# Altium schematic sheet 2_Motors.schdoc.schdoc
size 309 x 223 mm; Symbol: Sheet-Symbol_A4; Device: Sheet-Symbol_A4; @Project Name: AstrOnStep; @Page Count: 2; @Update Date: 2024-04-19; @Create Date: 2024-04-17; @Schematic Name: AstrOnStep SCH; @Page No: 2; @Page Name: Motors.AstrOnStep SCH; Company: EasyEDA.com; Reviewed: EasyEDA; Version: V0.1; Page Size: A4; Part Number: JLCPCB-002; Drawn: EasyEDA
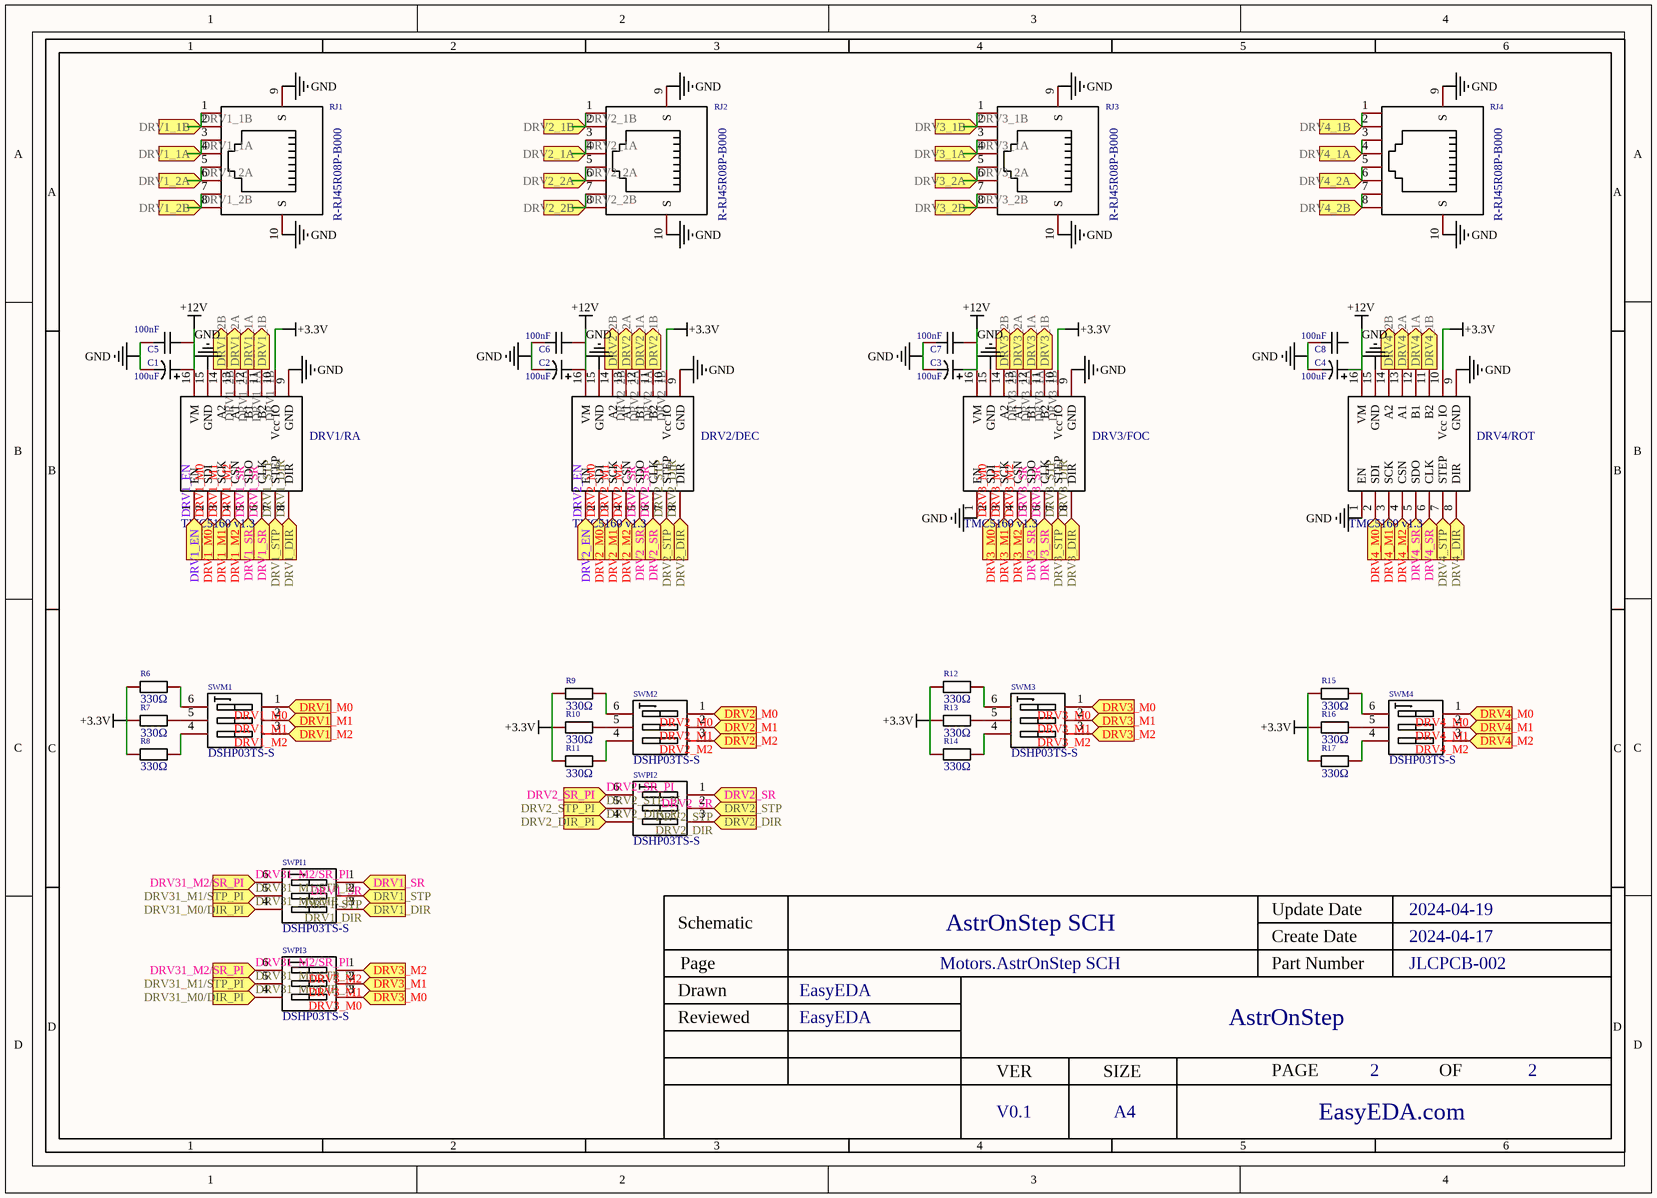
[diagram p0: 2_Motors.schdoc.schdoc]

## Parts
C1  100uF  [CAP-SMD_BD6.3-L6.6-W6.6-LS7.3-FD]
C2  100uF  [CAP-SMD_BD6.3-L6.6-W6.6-LS7.3-FD]
C3  100uF  [CAP-SMD_BD6.3-L6.6-W6.6-LS7.3-FD]
C4  100uF  [CAP-SMD_BD6.3-L6.6-W6.6-LS7.3-FD]
C5  100nF  [C0603]
C6  100nF  [C0603]
C7  100nF  [C0603]
C8  100nF  [C0603]
DRV1/RA  TMC5160 v1.3  [TMC5160]
DRV2/DEC  TMC5160 v1.3  [TMC5160]
DRV3/FOC  TMC5160 v1.3  [TMC5160]
DRV4/ROT  TMC5160 v1.3  [TMC5160]
R6  330Ω  [R0402]
R7  330Ω  [R0402]
R8  330Ω  [R0402]
R9  330Ω  [R0402]
R10  330Ω  [R0402]
R11  330Ω  [R0402]
R12  330Ω  [R0402]
R13  330Ω  [R0402]
R14  330Ω  [R0402]
R15  330Ω  [R0402]
R16  330Ω  [R0402]
R17  330Ω  [R0402]
RJ1  R-RJ45R08P-B000  [RJ45-TH_R-RJ45R08P-B000]
RJ2  R-RJ45R08P-B000  [RJ45-TH_R-RJ45R08P-B000]
RJ3  R-RJ45R08P-B000  [RJ45-TH_R-RJ45R08P-B000]
RJ4  R-RJ45R08P-B000  [RJ45-TH_R-RJ45R08P-B000]
SWM1  DSHP03TS-S  [SW-SMD_DSHP03TS-S]
SWM2  DSHP03TS-S  [SW-SMD_DSHP03TS-S]
SWM3  DSHP03TS-S  [SW-SMD_DSHP03TS-S]
SWM4  DSHP03TS-S  [SW-SMD_DSHP03TS-S]
SWPI1  DSHP03TS-S  [SW-SMD_DSHP03TS-S]
SWPI2  DSHP03TS-S  [SW-SMD_DSHP03TS-S]
SWPI3  DSHP03TS-S  [SW-SMD_DSHP03TS-S]

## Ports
DRV1_1A (in), DRV1_1A (out), DRV1_1B (in), DRV1_1B (out), DRV1_2A (in), DRV1_2A (out), DRV1_2B (in), DRV1_2B (out), DRV1_DIR (in), DRV1_EN (in), DRV1_M0 (in), DRV1_M1 (in), DRV1_M2 (in), DRV1_SR (in), DRV1_STP (in), DRV2_1A (in), DRV2_1A (out), DRV2_1B (in), DRV2_1B (out), DRV2_2A (in), DRV2_2A (out), DRV2_2B (in), DRV2_2B (out), DRV2_DIR (in), DRV2_DIR_PI (in), DRV2_EN (in), DRV2_M0 (in), DRV2_M1 (in), DRV2_M2 (in), DRV2_SR (in), DRV2_SR_PI (in), DRV2_STP (in), DRV2_STP_PI (in), DRV3_1A (in), DRV3_1A (out), DRV3_1B (in), DRV3_1B (out), DRV3_2A (in), DRV3_2A (out), DRV3_2B (in), DRV3_2B (out), DRV3_DIR (in), DRV3_M0 (in), DRV3_M1 (in), DRV3_M2 (in), DRV3_SR (in), DRV3_STP (in), DRV4_1A (in), DRV4_1A (out), DRV4_1B (in), DRV4_1B (out), DRV4_2A (in), DRV4_2A (out), DRV4_2B (in), DRV4_2B (out), DRV4_DIR (in), DRV4_M0 (in), DRV4_M1 (in), DRV4_M2 (in), DRV4_SR (in), DRV4_STP (in), DRV31_M0/DIR_PI (in), DRV31_M1/STP_PI (in), DRV31_M2/SR_PI (in)

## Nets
+3.3V: DRV1/RA.10(Vcc_IO) DRV2/DEC.10(Vcc_IO) DRV3/FOC.10(Vcc_IO) DRV4/ROT.10(Vcc_IO) R6.2 R7.2 R8.2 R9.2 R10.2 R11.2 R12.2 R13.2 R14.2 R15.2 R16.2 R17.2
+12V: C1.1 C2.1 C3.1 C4.1 C5.1 C6.1 C7.1 DRV1/RA.16(VM) DRV2/DEC.16(VM) DRV3/FOC.16(VM) DRV4/ROT.16(VM)
GND: C1.2 C2.2 C3.2 C4.2 C5.2 C6.2 C7.2 C8.2 DRV1/RA.9(GND) DRV1/RA.15(GND) DRV2/DEC.9(GND) DRV2/DEC.15(GND) DRV3/FOC.1(EN) DRV3/FOC.9(GND) DRV3/FOC.15(GND) DRV4/ROT.1(EN) DRV4/ROT.9(GND) DRV4/ROT.15(GND) RJ1.9(S) RJ1.10(S) RJ2.9(S) RJ2.10(S) RJ3.9(S) RJ3.10(S) RJ4.9(S) RJ4.10(S)
DRV1_1A: DRV1/RA.12(B1) RJ1.3 RJ1.4 ; port DRV1_1A
DRV1_1B: DRV1/RA.11(B2) RJ1.1 RJ1.2 ; port DRV1_1B
DRV1_2A: DRV1/RA.13(A1) RJ1.5 RJ1.6 ; port DRV1_2A
DRV1_2B: DRV1/RA.14(A2) RJ1.7 RJ1.8 ; port DRV1_2B
DRV1_DIR: DRV1/RA.8(DIR) SWPI1.3 ; port DRV1_DIR
DRV1_EN: DRV1/RA.1(EN) ; port DRV1_EN
DRV1_M0: DRV1/RA.2(SDI) SWM1.1 ; port DRV1_M0
DRV1_M1: DRV1/RA.3(SCK) SWM1.2 ; port DRV1_M1
DRV1_M2: DRV1/RA.4(CSN) SWM1.3 ; port DRV1_M2
DRV1_SR: DRV1/RA.5(SDO) DRV1/RA.6(CLK) SWPI1.1 ; port DRV1_SR
DRV1_STP: DRV1/RA.7(STEP) SWPI1.2 ; port DRV1_STP
DRV2_1A: DRV2/DEC.12(B1) RJ2.3 RJ2.4 ; port DRV2_1A
DRV2_1B: DRV2/DEC.11(B2) RJ2.1 RJ2.2 ; port DRV2_1B
DRV2_2A: DRV2/DEC.13(A1) RJ2.5 RJ2.6 ; port DRV2_2A
DRV2_2B: DRV2/DEC.14(A2) RJ2.7 RJ2.8 ; port DRV2_2B
DRV2_DIR: DRV2/DEC.8(DIR) SWPI2.3 ; port DRV2_DIR
DRV2_DIR_PI: SWPI2.4 ; port DRV2_DIR_PI
DRV2_EN: DRV2/DEC.1(EN) ; port DRV2_EN
DRV2_M0: DRV2/DEC.2(SDI) SWM2.1 ; port DRV2_M0
DRV2_M1: DRV2/DEC.3(SCK) SWM2.2 ; port DRV2_M1
DRV2_M2: DRV2/DEC.4(CSN) SWM2.3 ; port DRV2_M2
DRV2_SR: DRV2/DEC.5(SDO) DRV2/DEC.6(CLK) SWPI2.1 ; port DRV2_SR
DRV2_SR_PI: SWPI2.6 ; port DRV2_SR_PI
DRV2_STP: DRV2/DEC.7(STEP) SWPI2.2 ; port DRV2_STP
DRV2_STP_PI: SWPI2.5 ; port DRV2_STP_PI
DRV3_1A: DRV3/FOC.12(B1) RJ3.3 RJ3.4 ; port DRV3_1A
DRV3_1B: DRV3/FOC.11(B2) RJ3.1 RJ3.2 ; port DRV3_1B
DRV3_2A: DRV3/FOC.13(A1) RJ3.5 RJ3.6 ; port DRV3_2A
DRV3_2B: DRV3/FOC.14(A2) RJ3.7 RJ3.8 ; port DRV3_2B
DRV3_DIR: DRV3/FOC.8(DIR) ; port DRV3_DIR
DRV3_M0: DRV3/FOC.2(SDI) SWM3.1 SWPI3.3 ; port DRV3_M0
DRV3_M1: DRV3/FOC.3(SCK) SWM3.2 SWPI3.2 ; port DRV3_M1
DRV3_M2: DRV3/FOC.4(CSN) SWM3.3 SWPI3.1 ; port DRV3_M2
DRV3_SR: DRV3/FOC.5(SDO) DRV3/FOC.6(CLK) ; port DRV3_SR
DRV3_STP: DRV3/FOC.7(STEP) ; port DRV3_STP
DRV4_1A: DRV4/ROT.12(B1) RJ4.3 RJ4.4 ; port DRV4_1A
DRV4_1B: DRV4/ROT.11(B2) RJ4.1 RJ4.2 ; port DRV4_1B
DRV4_2A: DRV4/ROT.13(A1) RJ4.5 RJ4.6 ; port DRV4_2A
DRV4_2B: DRV4/ROT.14(A2) RJ4.7 RJ4.8 ; port DRV4_2B
DRV4_DIR: DRV4/ROT.8(DIR) ; port DRV4_DIR
DRV4_M0: DRV4/ROT.2(SDI) SWM4.1 ; port DRV4_M0
DRV4_M1: DRV4/ROT.3(SCK) SWM4.2 ; port DRV4_M1
DRV4_M2: DRV4/ROT.4(CSN) SWM4.3 ; port DRV4_M2
DRV4_SR: DRV4/ROT.5(SDO) DRV4/ROT.6(CLK) ; port DRV4_SR
DRV4_STP: DRV4/ROT.7(STEP) ; port DRV4_STP
DRV31_M0/DIR_PI: SWPI1.4 SWPI3.4 ; port DRV31_M0/DIR_PI
DRV31_M1/STP_PI: SWPI1.5 SWPI3.5 ; port DRV31_M1/STP_PI
DRV31_M2/SR_PI: SWPI1.6 SWPI3.6 ; port DRV31_M2/SR_PI
NetR6_1: R6.1 SWM1.6
NetR7_1: R7.1 SWM1.5
NetR8_1: R8.1 SWM1.4
NetR9_1: R9.1 SWM2.6
NetR10_1: R10.1 SWM2.5
NetR11_1: R11.1 SWM2.4
NetR12_1: R12.1 SWM3.6
NetR13_1: R13.1 SWM3.5
NetR14_1: R14.1 SWM3.4
NetR15_1: R15.1 SWM4.6
NetR16_1: R16.1 SWM4.5
NetR17_1: R17.1 SWM4.4

Not connected (* = marked no-connect by the designer): C8 1

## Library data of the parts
C1-C4 = RST100UF25V004: Manufacturer: KNSCHA(科尼盛); Add into BOM: yes; Tolerance: ±20%; Ripple Current: 88mA@120Hz; Lifetime @ Temp: 2000hrs@105℃; Description: Capacitance: Tolerance:±20% Tolerance:±20% Rated Voltage: Ripple Current:88mA@120Hz Equivalent Series Resistance(ESR):- φD: L: Lifetime @ Temp:2000hrs@105℃ Operating Temperature:-40℃~+105℃ Operating Temperature:-40℃~+105℃
C5-C8 = CC0603KRX7R9BB104: Manufacturer: YAGEO(国巨); Add into BOM: yes; Tolerance: ±10%; Description: Capacitance:Tolerance:±10%Tolerance:±10%VoltageRated:TemperatureCoefficient:
DRV1/RA DRV2/DEC DRV3/FOC DRV4/ROT = TMC5160 v1.3: Manufacturer: Bigtreetech; Add into BOM: no; Convert to PCB: yes
R6-R17 = 0402WGF3300TCE: Manufacturer: UNI-ROYAL(厚声); Add into BOM: yes; Tolerance: ±1%; Temperature Coefficient: ±100ppm/℃; Description: Type:Thick Film Resistors Resistance: Tolerance:±1% Tolerance:±1% Power(Watts): Overload Voltage (Max): Temperature Coefficient:±100ppm/℃ Temperature Coefficient:±100ppm/℃ Operating Temperature Range:-55℃~+155℃ Operating Temperature Range:-55℃~+155℃
RJ1-RJ4 = R-RJ45R08P-B000: Manufacturer: Ckmtw(灿科盟); Add into BOM: yes; Connector Type: RJReceptacle; USOC Codes: RJ45; Number of Ports: 1; Shielding: 有屏蔽; LED: 不带LED; Description: Connector Type:RJReceptacle USOC Codes:RJ45 Number of Ports:1 Mounting Style:Right-Angle Shielding:有屏蔽 LED:不带LED Ratings:- Operating Temperature Range:0℃~+70℃ Operating Temperature Range:0℃~+70℃
SWM1-SWM4 SWPI1-SWPI3 = DSHP03TS-S: Manufacturer: XKB Connectivity(中国星坤); Add into BOM: yes; Circuit: SPST; Number of Positions: 3Bit; Pin Style: Gull Wing; Current Rating: 25mA; Voltage Rating: 24V; Operating Life: 3千次; Description: Type:平拨,凹槽式 Circuit:SPST Number of Positions:3Bit Pin Style:Gull Wing Lead Pitch:1.27mm Current Rating:25mA Voltage Rating:24V Operating Temperature:-20℃~+70℃ Operating Temperature:-20℃~+70℃ Operating Life:3千次 Color:Black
